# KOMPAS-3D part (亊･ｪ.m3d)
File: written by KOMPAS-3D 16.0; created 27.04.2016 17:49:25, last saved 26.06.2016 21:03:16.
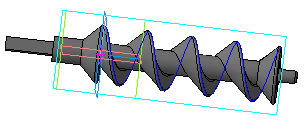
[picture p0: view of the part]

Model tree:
1. Эскиз:1
2. Операция выдавливания:1
     Расстояние 1 = 125; Расстояние 2 = 115; Угол 2 = 16
3. Эскиз:2
4. Спираль цилиндрическая:1
     Число витков = 4; Шаг = 28; Высота = 112; Диаметр 1 = 36; Диаметр 2 = 10
5. Параллельная плоскость:1
6. Эскиз:3
7. Кинематическая операция:1
8. Скругление:1
     Радиус = 1
9. Скругление:2
     Радиус = 3
10. Операция вращения:1
     Угол 1 = 360
11. Операция вращения:3
     Угол 1 = 360
12. Эскиз:4
13. Операция выдавливания:3
     Расстояние 1 = 30; Расстояние 2 = 115; Угол 2 = 16
14. Вырезать элемент выдавливания:1
     Расстояние 2 = 10
15. Эскиз:5
16. Операция выдавливания:4
     Расстояние 1 = 30; Расстояние 2 = 115; Угол 2 = 16
17. Эскиз:6
18. Операция выдавливания:5
     Расстояние 1 = 2; Расстояние 2 = 115; Угол 2 = 16
19. Эскиз:7
20. Операция выдавливания:6
     Расстояние 1 = 10; Расстояние 2 = 115; Угол 2 = 16
21. Фаска:1
     Угол = 49; Длина 1 = 1; Длина 2 = 1.15037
